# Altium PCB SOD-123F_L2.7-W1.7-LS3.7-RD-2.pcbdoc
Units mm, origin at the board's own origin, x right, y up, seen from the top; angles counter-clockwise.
Board outline 17.05 x 14.56 mm, 2 copper layers (Top Layer, Bottom Layer), stack 0 mm thick; 1 components, 0 nets, 2 pads, 0 vias.
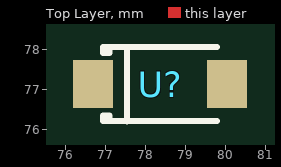
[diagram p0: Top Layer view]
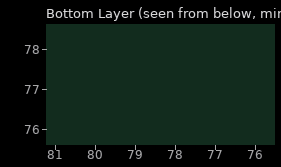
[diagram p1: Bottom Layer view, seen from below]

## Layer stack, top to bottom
Top Layer: signal copper (thickness not stored)
Bottom Layer: signal copper (thickness not stored)

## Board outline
86.9,69.85 69.85,69.85 69.85,84.406 86.9,84.406

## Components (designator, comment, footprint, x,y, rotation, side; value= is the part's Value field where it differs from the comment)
U? "" SOD-123F_L2.7-W1.7-LS3.7-RD-2 78.375,77.13 r0 top

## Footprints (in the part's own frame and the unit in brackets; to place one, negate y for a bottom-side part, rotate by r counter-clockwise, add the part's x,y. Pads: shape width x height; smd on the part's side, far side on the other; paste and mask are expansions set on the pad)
SOD-123F_L2.7-W1.7-LS3.7-RD-2 [mm]
  rect 1x1.2 smd: 1(-1.675,0) 2(1.675,0)
  silkscreen extent -1.43,-0.93 1.43,0.93

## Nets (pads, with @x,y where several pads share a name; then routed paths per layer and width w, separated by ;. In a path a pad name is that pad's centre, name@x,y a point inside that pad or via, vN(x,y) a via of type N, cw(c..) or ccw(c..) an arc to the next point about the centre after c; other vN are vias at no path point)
pads on no net: U?.1 U?.2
